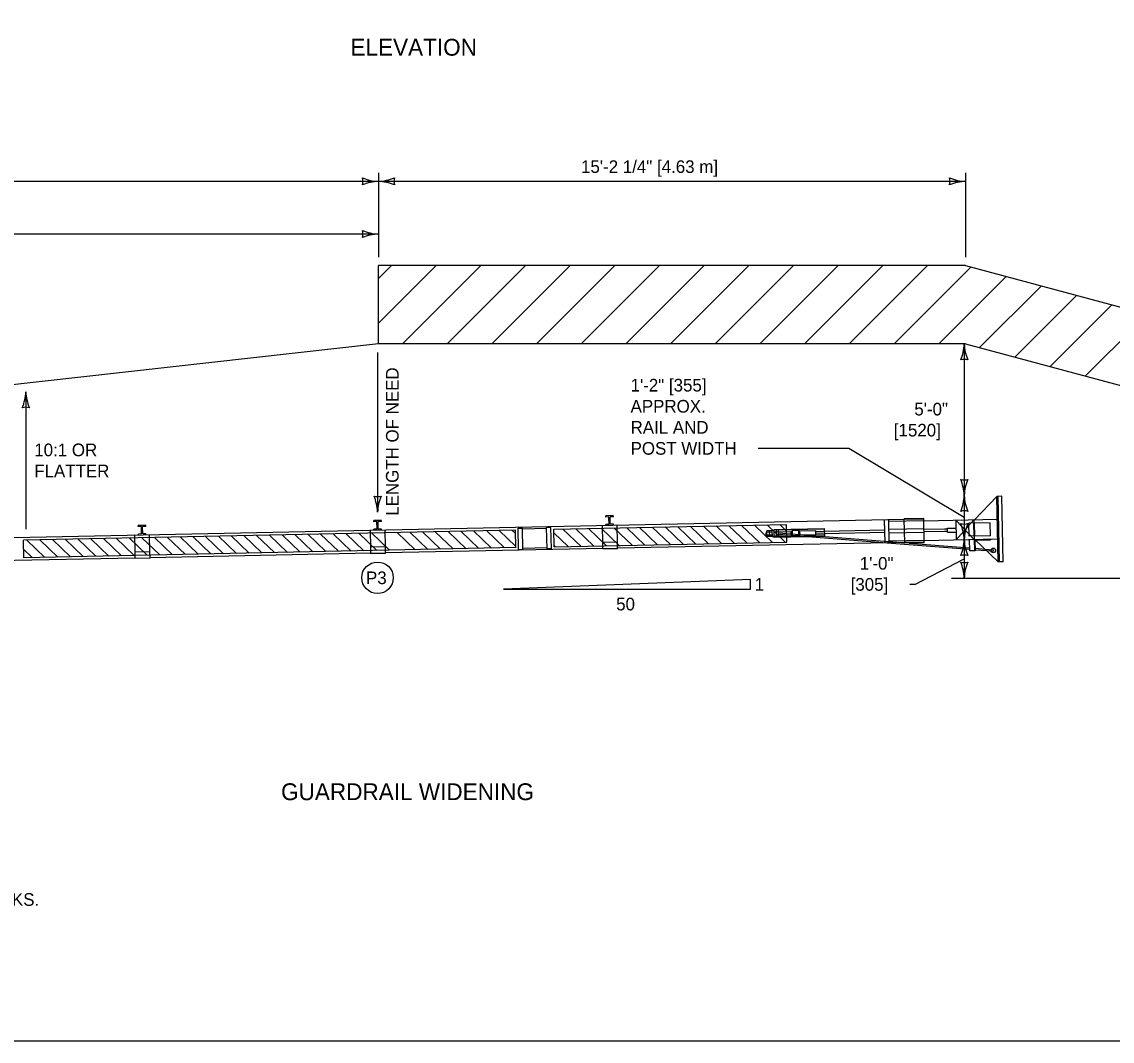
# Model space of a CAD drawing. Extents: x 49991.4 to 50021, y 49987.6 to 50011.4.
# Drawn here: x 50006.18 to 50011.36, y 49987.8 to 49992.64 of the extents above; entities that cross this region are included whole.
import ezdxf

# ---------------------------------------------------------------- set-up
doc = ezdxf.new("R2010")
doc.units = 0
for name, color, linetype in [('Level 1', 7, 'Continuous'), ('Level 2', 7, 'Continuous'), ('Level 3', 7, 'Continuous'), ('Level 4', 7, 'Continuous'), ('Level 5', 7, 'Continuous')]:
    doc.layers.add(name, color=color, linetype=linetype)

msp = doc.modelspace()

# ---------------------------------------------------------------- linework, layer by layer
at = {"layer": 'Level 1'}
for p, q in [((50007.8759, 49991.1095), (50007.8759, 49991.481)), ((50010.6629, 49991.481), (50007.8759, 49991.481)), ((50007.8759, 49991.2074), (50008.1495, 49991.481)), ((50007.8759, 49991.4195), (50007.9374, 49991.481)), ((50007.99, 49991.1095), (50008.3615, 49991.481)), ((50008.2022, 49991.1095), (50008.5737, 49991.481)), ((50008.4143, 49991.1095), (50008.7858, 49991.481)), ((50008.6263, 49991.1095), (50008.9978, 49991.481)), ((50008.8385, 49991.1095), (50009.21, 49991.481)), ((50009.0507, 49991.1095), (50009.4222, 49991.481)), ((50009.2627, 49991.1095), (50009.6342, 49991.481)), ((50009.4749, 49991.1095), (50009.8464, 49991.481)), ((50009.6871, 49991.1095), (50010.0586, 49991.481)), ((50009.8991, 49991.1095), (50010.2706, 49991.481)), ((50010.1113, 49991.1095), (50010.4828, 49991.481)), ((50010.3234, 49991.1095), (50010.6881, 49991.4742)), ((50010.6629, 49991.481), (50016.1992, 49989.9977)), ((50010.5356, 49991.1095), (50010.8555, 49991.4294)), ((50010.7299, 49991.0916), (50011.0229, 49991.3846)), ((50010.8971, 49991.0468), (50011.1901, 49991.3398)), ((50011.0644, 49991.0019), (50011.3574, 49991.2949)), ((50011.2318, 49990.9571), (50011.5248, 49991.2501)), ((50007.8759, 49991.1095), (50001.1481, 49990.3564)), ((50010.6629, 49991.1095), (50007.8759, 49991.1095)), ((50010.6629, 49991.1095), (50014.8128, 49989.9977)), ((50010.8121, 49990.3856), (50010.7057, 49990.2746)), ((50010.8351, 49990.386), (50010.8121, 49990.3856)), ((50010.8186, 49990.075), (50010.8121, 49990.3856)), ((50010.8245, 49990.0751), (50010.818, 49990.3857)), ((50010.8415, 49990.0754), (50010.8351, 49990.386)), ((50010.3716, 49990.2756), (50006.023, 49990.1867)), ((50006.7715, 49990.2485), (50006.7352, 49990.2478)), ((50006.7353, 49990.2423), (50006.7352, 49990.2478)), ((50006.7715, 49990.243), (50006.7715, 49990.2485)), ((50007.8897, 49990.2715), (50007.8536, 49990.2707)), ((50007.8537, 49990.2651), (50007.8536, 49990.2707)), ((50007.8689, 49990.2655), (50007.8537, 49990.2651)), ((50007.8696, 49990.2302), (50007.8689, 49990.2655)), ((50007.8898, 49990.2659), (50007.8745, 49990.2656)), ((50007.8752, 49990.2302), (50007.8745, 49990.2656)), ((50007.8898, 49990.2659), (50007.8897, 49990.2715)), ((50008.9909, 49990.294), (50008.9547, 49990.2932)), ((50008.9549, 49990.2876), (50008.9547, 49990.2932)), ((50008.9703, 49990.2879), (50008.9549, 49990.2876)), ((50008.9709, 49990.2526), (50008.9556, 49990.2523)), ((50008.9557, 49990.2466), (50008.9556, 49990.2523)), ((50008.9709, 49990.2526), (50008.9703, 49990.2879)), ((50008.991, 49990.2884), (50008.9759, 49990.288)), ((50008.9766, 49990.2528), (50008.9759, 49990.288)), ((50008.9918, 49990.2531), (50008.9766, 49990.2528)), ((50008.991, 49990.2884), (50008.9909, 49990.294)), ((50008.9919, 49990.2474), (50008.9918, 49990.2531)), ((50010.4648, 49990.2812), (50010.3715, 49990.2794)), ((50010.374, 49990.1632), (50010.3715, 49990.2794)), ((50010.4672, 49990.1651), (50010.4648, 49990.2812)), ((50010.465, 49990.2697), (50010.8144, 49990.2768)), ((50010.6165, 49990.2728), (50010.7038, 49990.1814)), ((50010.6165, 49990.2728), (50010.6184, 49990.1797)), ((50010.7019, 49990.2745), (50010.6184, 49990.1797)), ((50010.7798, 49990.2607), (50010.679, 49990.2586)), ((50010.6802, 49990.1963), (50010.679, 49990.2586)), ((50010.7019, 49990.2745), (50010.7038, 49990.1814)), ((50010.7035, 49990.1968), (50010.7022, 49990.2591)), ((50010.7074, 49990.1969), (50010.7061, 49990.2592)), ((50010.7811, 49990.1984), (50010.7798, 49990.2607)), ((50006.7507, 49990.2427), (50006.7353, 49990.2423)), ((50006.7515, 49990.2073), (50006.7361, 49990.2069)), ((50006.7361, 49990.2013), (50006.7361, 49990.2069)), ((50006.7515, 49990.2073), (50006.7507, 49990.2427)), ((50006.7715, 49990.243), (50006.7562, 49990.2428)), ((50006.757, 49990.2073), (50006.7562, 49990.2428)), ((50006.7723, 49990.2077), (50006.757, 49990.2073)), ((50006.7724, 49990.202), (50006.7723, 49990.2077)), ((50007.8696, 49990.2302), (50007.8544, 49990.2299)), ((50007.8546, 49990.2241), (50007.8544, 49990.2299)), ((50007.8905, 49990.2306), (50007.8752, 49990.2302)), ((50007.8906, 49990.2249), (50007.8905, 49990.2306)), ((50010.5623, 49990.2302), (50010.4659, 49990.2282)), ((50010.5626, 49990.2189), (50010.4661, 49990.2169)), ((50010.5777, 49990.2306), (50010.5623, 49990.2302)), ((50010.578, 49990.2193), (50010.5626, 49990.2189)), ((50010.5776, 49990.2344), (50010.6172, 49990.2351)), ((50010.578, 49990.2155), (50010.5776, 49990.2344)), ((50010.578, 49990.2155), (50010.6176, 49990.2162)), ((50010.7811, 49990.1984), (50010.6802, 49990.1963)), ((50007.9092, 49990.1457), (50007.8393, 49990.1442)), ((50007.8399, 49990.1133), (50007.8393, 49990.1442)), ((50007.9098, 49990.1147), (50007.9092, 49990.1457)), ((50009.0104, 49990.1682), (50008.9405, 49990.1667)), ((50008.9412, 49990.1357), (50008.9406, 49990.1666)), ((50009.0111, 49990.1371), (50009.0104, 49990.1682)), ((50010.3739, 49990.1669), (50009.011, 49990.1391)), ((50010.2911, 49990.1652), (50010.6815, 49990.1344)), ((50010.3575, 49990.1666), (50010.374, 49990.1654)), ((50010.4672, 49990.1651), (50010.374, 49990.1632)), ((50010.3952, 49990.1636), (50010.6813, 49990.1411)), ((50010.467, 49990.1767), (50010.8163, 49990.1837)), ((50010.6805, 49990.181), (50010.6816, 49990.1266)), ((50010.7038, 49990.1814), (50010.705, 49990.1271)), ((50010.8186, 49990.075), (50010.7077, 49990.1815)), ((50010.7117, 49990.1777), (50010.7078, 49990.1776)), ((50010.7078, 49990.1776), (50010.7089, 49990.1272)), ((50006.7216, 49990.0924), (50006.0252, 49990.078)), ((50006.791, 49990.1229), (50006.721, 49990.1214)), ((50006.7216, 49990.0903), (50006.721, 49990.1214)), ((50006.7916, 49990.0919), (50006.7216, 49990.0904)), ((50006.7916, 49990.0919), (50006.791, 49990.1229)), ((50007.8399, 49990.1155), (50006.7916, 49990.0939)), ((50007.9098, 49990.1147), (50007.8399, 49990.1133)), ((50008.9412, 49990.1376), (50007.9098, 49990.1167)), ((50009.0111, 49990.1371), (50008.9412, 49990.1357)), ((50010.7089, 49990.1272), (50010.6816, 49990.1266)), ((50010.7086, 49990.1389), (50010.7558, 49990.1353)), ((50010.7088, 49990.1322), (50010.7635, 49990.1279)), ((50010.8415, 49990.0754), (50010.8186, 49990.075))]:
    msp.add_line(p, q, dxfattribs=at)
msp.add_lwpolyline([(49999.3835, 49998.9992), (50016.7501, 49998.9992), (50016.7501, 49987.7988), (49999.3835, 49987.7988)], close=True, dxfattribs=at)
msp.add_lwpolyline([(50010.5963, 49989.9977), (50016.1992, 49989.9977)], dxfattribs=at)
at = {"layer": 'Level 2'}
msp.add_circle((50007.8715, 49989.9989), 0.075, dxfattribs=at)
at = {"layer": 'Level 3'}
for p, q in [((50007.8759, 49991.921), (50007.8759, 49991.521)), ((50010.6629, 49991.921), (50010.6629, 49991.521)), ((50007.8759, 49991.881), (50001.1481, 49991.881)), ((50010.6629, 49991.881), (50007.8759, 49991.881)), ((50007.8759, 49991.631), (50001.7075, 49991.631)), ((50010.6568, 49991.1095), (50010.6568, 49990.3903)), ((50007.8717, 49991.069), (50007.8717, 49990.3111)), ((50006.202, 49990.8821), (50006.202, 49990.2304)), ((50010.1085, 49990.6134), (50009.6787, 49990.6134)), ((50010.6568, 49990.2854), (50010.1085, 49990.6134)), ((50010.6568, 49990.3903), (50010.6568, 49990.1805)), ((50010.6568, 49990.1805), (50010.6568, 49989.9977)), ((50010.4215, 49989.9676), (50010.6568, 49990.0891)), ((50009.6416, 49989.991), (50008.4697, 49989.9442)), ((50009.6416, 49989.9442), (50009.6416, 49989.991)), ((50008.4697, 49989.9442), (50009.6416, 49989.9442)), ((50010.4215, 49989.9676), (50010.3979, 49989.9676))]:
    msp.add_line(p, q, dxfattribs=at)
for centre, radius, start, end in [((50007.8851, 49992.1031), 0.2223, 247.456, 267.6395), ((50007.7477, 49991.881), 0.0548, 342.1388, 17.8612), ((50007.8874, 49991.6483), 0.233, 92.8273, 112.0772), ((50007.8644, 49992.1137), 0.233, 272.8273, 292.0772), ((50007.8667, 49991.6589), 0.2223, 67.456, 87.6395), ((50008.0041, 49991.881), 0.0548, 162.1388, 197.8612), ((50010.6721, 49992.1031), 0.2223, 247.456, 267.6395), ((50010.5347, 49991.881), 0.0548, 342.1388, 17.8612), ((50010.6744, 49991.6483), 0.233, 92.8273, 112.0772), ((50007.8851, 49991.8531), 0.2223, 247.456, 267.6395), ((50007.7477, 49991.631), 0.0548, 342.1388, 17.8612), ((50007.8874, 49991.3983), 0.233, 92.8273, 112.0772), ((50010.4347, 49991.1187), 0.2223, 337.456, 357.6395), ((50010.8895, 49991.121), 0.233, 182.8273, 202.0772), ((50010.6568, 49990.9813), 0.0548, 72.1388, 107.8612), ((50005.9799, 49990.8913), 0.2223, 337.456, 357.6395), ((50006.4347, 49990.8936), 0.233, 182.8273, 202.0772), ((50006.202, 49990.7539), 0.0548, 72.1388, 107.8612), ((50010.6568, 49990.5186), 0.0548, 252.1388, 287.8612), ((50010.4241, 49990.3789), 0.233, 2.8273, 22.0772), ((50010.8789, 49990.3812), 0.2223, 157.456, 177.6395), ((50007.8717, 49990.4393), 0.0548, 252.1388, 287.8612), ((50007.639, 49990.2996), 0.233, 2.8273, 22.0772), ((50008.0938, 49990.3019), 0.2223, 157.456, 177.6395), ((50010.4347, 49990.3995), 0.2223, 337.456, 357.6395), ((50010.8895, 49990.4018), 0.233, 182.8273, 202.0772), ((50010.6568, 49990.2621), 0.0548, 72.1388, 107.8612), ((50010.6568, 49990.3087), 0.0548, 252.1388, 287.8612), ((50010.4241, 49990.169), 0.233, 2.8273, 22.0772), ((50010.8789, 49990.1713), 0.2223, 157.456, 177.6395), ((50010.4347, 49990.1897), 0.2223, 337.456, 357.6395), ((50010.8895, 49990.192), 0.233, 182.8273, 202.0772), ((50010.6568, 49990.0523), 0.0548, 72.1388, 107.8612), ((50010.6568, 49990.1259), 0.0548, 252.1388, 287.8612), ((50010.4241, 49989.9862), 0.233, 2.8273, 22.0772), ((50010.8789, 49989.9885), 0.2223, 157.456, 177.6395)]:
    msp.add_arc(centre, radius, start, end, dxfattribs=at)
at = {"layer": 'Level 4'}
for p, q in [((50009.0104, 49990.1682), (50009.0089, 49990.2477)), ((50009.8145, 49990.1679), (50009.8129, 49990.2519)), ((50010.2808, 49990.1651), (50010.2785, 49990.2737)), ((50010.3004, 49990.1655), (50010.2982, 49990.2741)), ((50010.465, 49990.2697), (50010.2984, 49990.2664)), ((50010.4649, 49990.2774), (50010.3716, 49990.2756)), ((50008.5266, 49990.2257), (50006.1914, 49990.1779)), ((50006.721, 49990.1214), (50006.7194, 49990.2009)), ((50006.791, 49990.1229), (50006.7894, 49990.2024)), ((50007.8393, 49990.1442), (50007.8377, 49990.2238)), ((50007.9092, 49990.1457), (50007.9075, 49990.2252)), ((50008.5283, 49990.1418), (50008.5266, 49990.2256)), ((50008.5394, 49990.2347), (50008.5601, 49990.2351)), ((50008.5414, 49990.1329), (50008.5394, 49990.2347)), ((50008.5621, 49990.1334), (50008.5601, 49990.2351)), ((50008.674, 49990.2323), (50008.5601, 49990.2299)), ((50008.6947, 49990.2378), (50008.674, 49990.2375)), ((50008.6761, 49990.1357), (50008.674, 49990.2375)), ((50008.6967, 49990.1361), (50008.6947, 49990.2378)), ((50008.7095, 49990.1455), (50008.7078, 49990.2293)), ((50008.9405, 49990.1667), (50008.9389, 49990.2463)), ((50009.7198, 49990.2156), (50009.7171, 49990.2137)), ((50009.7171, 49990.2022), (50009.7171, 49990.2137)), ((50009.7201, 49990.2006), (50009.7171, 49990.2022)), ((50009.7456, 49990.222), (50009.7197, 49990.2214)), ((50009.7203, 49990.1946), (50009.7197, 49990.2214)), ((50009.7201, 49990.2006), (50009.7198, 49990.2156)), ((50009.7198, 49990.2156), (50009.7198, 49990.2156)), ((50009.7457, 49990.2154), (50009.7198, 49990.2148)), ((50009.746, 49990.2018), (50009.7201, 49990.2013)), ((50009.7461, 49990.1952), (50009.7203, 49990.1946)), ((50009.7332, 49990.1948), (50009.7326, 49990.2217)), ((50009.7461, 49990.1936), (50009.7454, 49990.2236)), ((50009.9927, 49990.2296), (50009.7543, 49990.2248)), ((50009.7551, 49990.1899), (50009.7543, 49990.2276)), ((50009.8354, 49990.2178), (50009.7545, 49990.2163)), ((50009.7549, 49990.2013), (50009.8357, 49990.2028)), ((50009.9933, 49990.1976), (50009.755, 49990.1927)), ((50009.7669, 49990.1929), (50009.7662, 49990.225)), ((50009.7757, 49990.1931), (50009.775, 49990.2252)), ((50009.7753, 49990.2125), (50010.3575, 49990.1666)), ((50009.7754, 49990.2058), (50010.2911, 49990.1652)), ((50009.841, 49990.2227), (50009.8354, 49990.2178)), ((50009.8357, 49990.2028), (50009.8354, 49990.2178)), ((50009.8357, 49990.2028), (50009.8414, 49990.1982)), ((50009.8711, 49990.2234), (50009.841, 49990.2227)), ((50009.8414, 49990.1982), (50009.841, 49990.2227)), ((50009.8715, 49990.1988), (50009.8414, 49990.1982)), ((50009.8711, 49990.2234), (50009.8769, 49990.2205)), ((50009.8715, 49990.1988), (50009.8711, 49990.2234)), ((50009.8715, 49990.1988), (50009.8773, 49990.2016)), ((50009.9522, 49990.222), (50009.8769, 49990.2205)), ((50009.8773, 49990.2016), (50009.8769, 49990.2205)), ((50009.9526, 49990.2031), (50009.8773, 49990.2016)), ((50009.9526, 49990.2031), (50009.9522, 49990.222)), ((50009.9523, 49990.2182), (50009.9929, 49990.2191)), ((50009.9525, 49990.207), (50009.9931, 49990.2079)), ((50009.9926, 49990.2324), (50009.9934, 49990.1947)), ((50010.2795, 49990.2252), (50009.9929, 49990.2191)), ((50010.2798, 49990.214), (50009.9931, 49990.2079)), ((50010.4658, 49990.2313), (50010.2991, 49990.2279)), ((50010.4662, 49990.214), (50010.2995, 49990.2106)), ((50006.1932, 49990.094), (50006.1914, 49990.1779)), ((50009.9934, 49990.1947), (50009.7551, 49990.1899)), ((50010.467, 49990.1767), (50010.3002, 49990.1732)), ((50010.4671, 49990.1689), (50010.3739, 49990.167)), ((50010.7117, 49990.1777), (50010.7815, 49990.1791)), ((50010.7814, 49990.183), (50010.7815, 49990.1791)), ((50008.5283, 49990.1421), (50006.1932, 49990.0939)), ((50008.5414, 49990.1329), (50008.5621, 49990.1334)), ((50008.6759, 49990.1408), (50008.562, 49990.1386)), ((50008.6967, 49990.1361), (50008.6761, 49990.1357)), ((50010.7558, 49990.1353), (50010.795, 49990.1322)), ((50010.7635, 49990.1279), (50010.7943, 49990.1255)), ((50010.795, 49990.1322), (50010.7943, 49990.1255))]:
    msp.add_line(p, q, dxfattribs=at)
for points in [[(50008.7078, 49990.2294), (50009.8129, 49990.252)], [(50009.7542, 49990.2238), (50009.7454, 49990.2236)], [(50009.7543, 49990.2276), (50009.9926, 49990.2324)], [(50008.7096, 49990.1454), (50009.8145, 49990.168)], [(50009.755, 49990.1937), (50009.7461, 49990.1936)], [(50006.7216, 49990.0924), (50006.7916, 49990.0939)], [(50006.7216, 49990.0924), (50006.7216, 49990.0924)], [(50007.8399, 49990.1153), (50007.9098, 49990.1167)], [(50008.9412, 49990.1377), (50009.011, 49990.1391)]]:
    msp.add_lwpolyline(points, dxfattribs=at)
msp.add_circle((50010.7947, 49990.1289), 0.0108, dxfattribs=at)
at = {"layer": 'Level 5'}
for p, q in [((50009.6857, 49990.1654), (50009.6001, 49990.2476)), ((50009.7464, 49990.1666), (50009.6607, 49990.2489)), ((50009.807, 49990.1678), (50009.7213, 49990.2501)), ((50009.8135, 49990.2211), (50009.7818, 49990.2514)), ((50007.1408, 49990.1135), (50007.0553, 49990.1956)), ((50007.2016, 49990.1147), (50007.1159, 49990.1968)), ((50007.262, 49990.116), (50007.1765, 49990.1981)), ((50007.3228, 49990.1172), (50007.2371, 49990.1993)), ((50007.3832, 49990.1185), (50007.2977, 49990.2005)), ((50007.4439, 49990.1197), (50007.3583, 49990.2018)), ((50007.5044, 49990.121), (50007.4189, 49990.203)), ((50007.565, 49990.1222), (50007.4794, 49990.2043)), ((50007.6256, 49990.1235), (50007.5401, 49990.2055)), ((50007.6861, 49990.1247), (50007.6006, 49990.2067)), ((50007.7467, 49990.126), (50007.6612, 49990.208)), ((50007.8073, 49990.1272), (50007.7218, 49990.2092)), ((50007.8678, 49990.1285), (50007.7824, 49990.2105)), ((50007.9285, 49990.1297), (50007.843, 49990.2117)), ((50008.0496, 49990.1322), (50007.9642, 49990.2142)), ((50008.1102, 49990.1335), (50008.0247, 49990.2154)), ((50008.1708, 49990.1347), (50008.0854, 49990.2167)), ((50008.2314, 49990.136), (50008.1459, 49990.2179)), ((50008.2919, 49990.1372), (50008.2065, 49990.2191)), ((50008.3528, 49990.1382), (50008.2671, 49990.2204)), ((50008.4131, 49990.1397), (50008.3277, 49990.2216)), ((50008.4737, 49990.141), (50008.3883, 49990.2229)), ((50008.5282, 49990.1479), (50008.4489, 49990.2241)), ((50008.5269, 49990.2086), (50008.5096, 49990.2254)), ((50008.7769, 49990.1469), (50008.7081, 49990.2128)), ((50008.8375, 49990.1481), (50008.7518, 49990.2303)), ((50008.8981, 49990.1494), (50008.8125, 49990.2315)), ((50008.9587, 49990.1506), (50008.873, 49990.2328)), ((50009.0193, 49990.1519), (50008.9336, 49990.234)), ((50009.0798, 49990.1531), (50008.9942, 49990.2353)), ((50009.1405, 49990.1543), (50009.0547, 49990.2365)), ((50009.201, 49990.1556), (50009.1155, 49990.2377)), ((50009.2617, 49990.1567), (50009.1759, 49990.239)), ((50009.3222, 49990.1581), (50009.2366, 49990.2402)), ((50009.3828, 49990.1592), (50009.2971, 49990.2415)), ((50009.4434, 49990.1604), (50009.3578, 49990.2427)), ((50009.5039, 49990.1618), (50009.4184, 49990.2439)), ((50009.5646, 49990.1629), (50009.4788, 49990.2452)), ((50009.6251, 49990.1642), (50009.5395, 49990.2464)), ((50006.2928, 49990.096), (50006.207, 49990.1782)), ((50006.3534, 49990.0972), (50006.2677, 49990.1795)), ((50006.4139, 49990.0985), (50006.3282, 49990.1807)), ((50006.4746, 49990.0997), (50006.3889, 49990.1819)), ((50006.5351, 49990.101), (50006.4494, 49990.1832)), ((50006.5958, 49990.1022), (50006.5101, 49990.1844)), ((50006.6564, 49990.1034), (50006.5706, 49990.1857)), ((50006.7169, 49990.1047), (50006.6312, 49990.1869)), ((50006.7775, 49990.1059), (50006.6918, 49990.1881)), ((50006.838, 49990.1072), (50006.7523, 49990.1894)), ((50006.8986, 49990.1085), (50006.813, 49990.1906)), ((50006.9592, 49990.1097), (50006.8735, 49990.1919)), ((50007.0198, 49990.111), (50006.9342, 49990.1931)), ((50007.0804, 49990.1122), (50006.9947, 49990.1943)), ((50008.7163, 49990.1456), (50008.7094, 49990.1523)), ((50006.2322, 49990.0947), (50006.1924, 49990.1328))]:
    msp.add_line(p, q, dxfattribs=at)

# ---------------------------------------------------------------- texts
at = {"layer": 'Level 2'}
for s, height, p in [('ELEVATION', 0.08, (50007.743, 49992.4779)), ('15\'-2 1/4" [4.63 m]', 0.06, (50008.8377, 49991.921)), ('1\'-2" [355]', 0.06, (50009.0729, 49990.8834)), ('APPROX.', 0.06, (50009.0729, 49990.7834)), ('5\'-0"', 0.06, (50010.4199, 49990.7699)), ('RAIL AND', 0.06, (50009.0729, 49990.6834)), ('[1520]', 0.06, (50010.3225, 49990.6699)), ('10:1 OR', 0.06, (50006.242, 49990.5762)), ('POST WIDTH', 0.06, (50009.0729, 49990.5834)), ('FLATTER', 0.06, (50006.242, 49990.4762)), ('1\'-0"', 0.06, (50010.161, 49990.0376)), ('P3', 0.06, (50007.8169, 49989.9689)), ('1', 0.06, (50009.6619, 49989.9376)), ('[305]', 0.06, (50010.1175, 49989.9376)), ('50', 0.06, (50009.0044, 49989.8442)), ('GUARDRAIL WIDENING', 0.08, (50007.4137, 49988.9432)), ('USE WOOD OR OTHER NCHRP 350/MASH APPROVED BLOCKS.', 0.06, (50003.8179, 49988.4416))]:
    msp.add_text(s, height=height, dxfattribs=at).set_placement(p)
msp.add_text('LENGTH OF NEED', height=0.06, rotation=90, dxfattribs=at).set_placement((50007.9717, 49990.2937))

doc.saveas('drawing.dxf')
